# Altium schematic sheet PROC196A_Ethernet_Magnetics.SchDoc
size 431 x 279 mm; Date: Not shown in title block; ApprovedBy: Not shown in title block; CheckedBy: Not shown in title block; Author: Not shown in title block; CompanyName: Not shown in title block; Engineer: Not shown in title block; Organization: Not shown in title block; Address1: Not shown in title block; Address2: Not shown in title block; Address3: Not shown in title block; Address4: Not shown in title block; DocumentNumber: 13; Revision: Use project parameter SCH_Rev; SheetNumber: 13; SheetTotal: 25; PageSetup: Record=PageOptions¦CenterHorizontal=True¦CenterVertical=True¦PrintScale=1.00¦XCorrection=1.00¦YCorrection=1.00¦PrintKind=0¦BorderSize=5000000¦LeftOffset=0¦BottomOffset=0¦Orientation=2¦PaperLength=1000¦PaperWidth=1000¦Scale=100¦PaperSource=15¦PrintQuality=600¦MediaType=1¦DitherType=10¦PaperKind=Letter¦PrintScaleMode=1
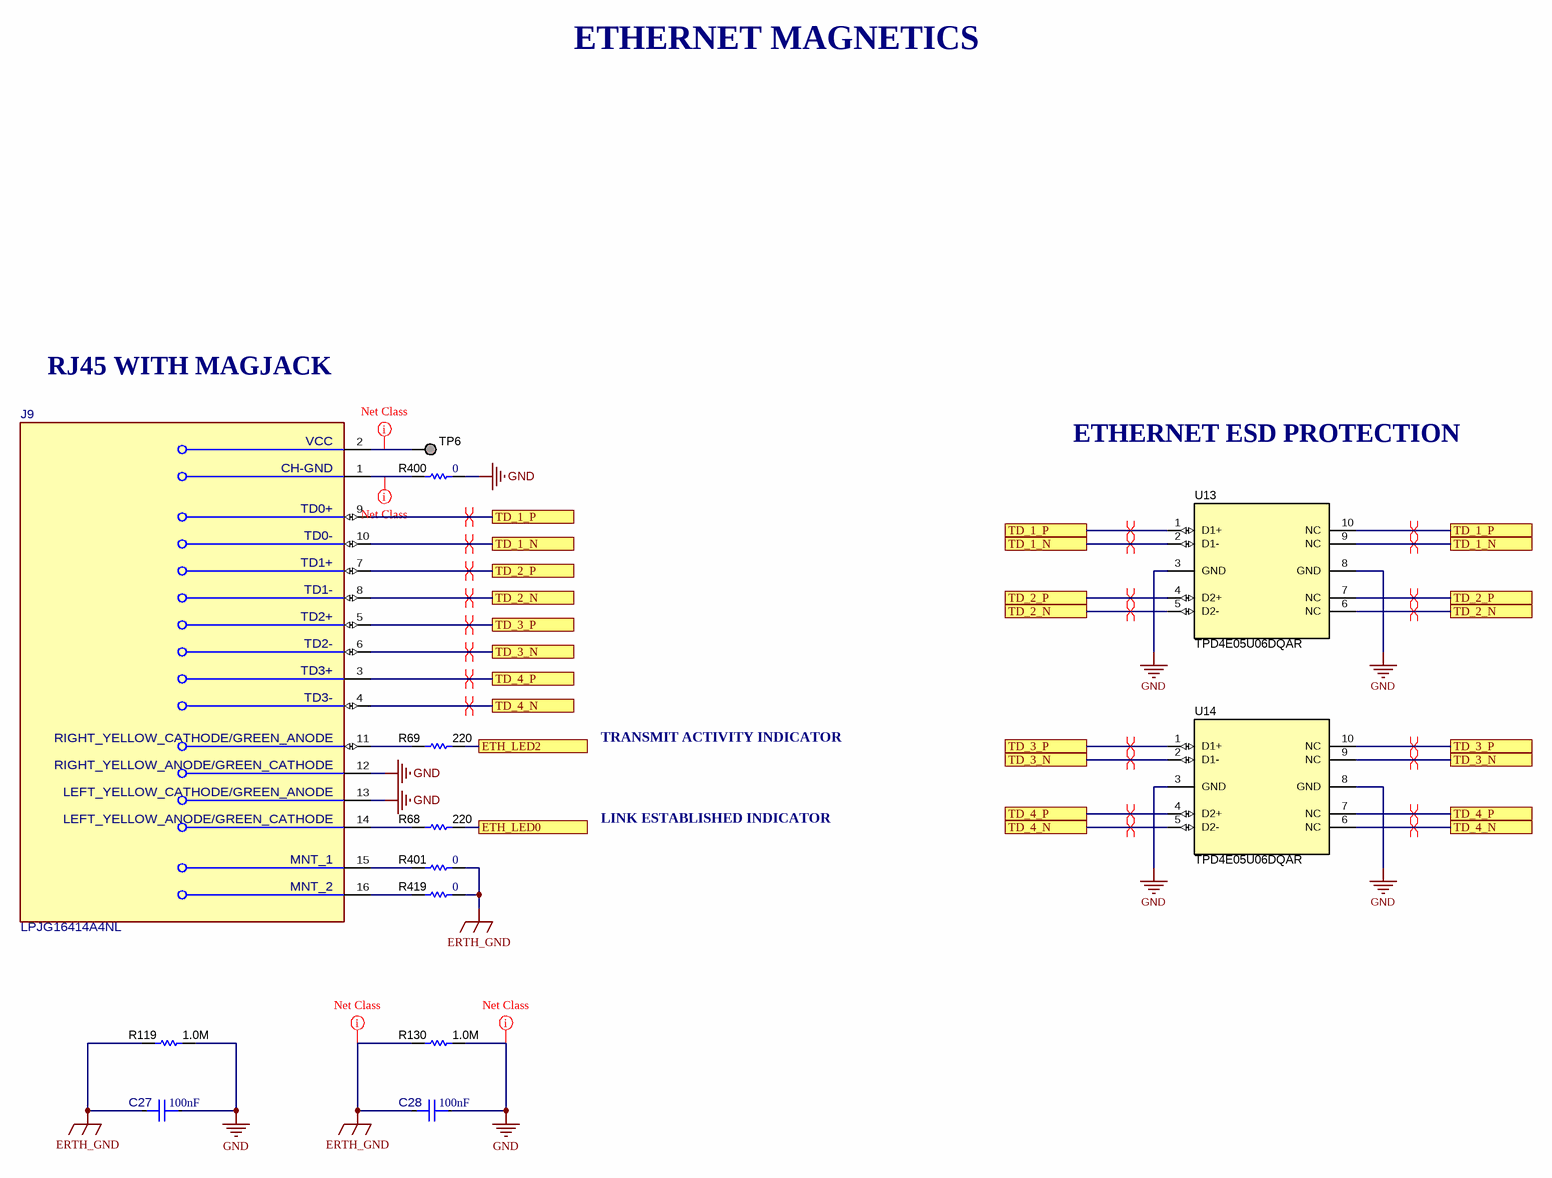
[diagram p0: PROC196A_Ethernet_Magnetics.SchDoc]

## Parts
C27  Cap_F: 100nF  [FP-C0603C104K4RACAUTO_0603-MFG]  (hidden comment: C0603C104K4RACAUTO)
C28  Cap_F: 100nF  [FP-C0603C104K4RACAUTO_0603-MFG]  (hidden comment: C0603C104K4RACAUTO)
J9  LPJG16414A4NL  [FP-LPJG16414A4NL_CONN_RJ45-MFG]
R68  ValueDisplayed: 220  [0402L]  (hidden comment: CRCW0402220RJNED)
R69  ValueDisplayed: 220  [0402L]  (hidden comment: CRCW0402220RJNED)
R119  ValueDisplayed: 1.0M  [1206L]  (hidden comment: CRCW12061M00JNEA)
R130  ValueDisplayed: 1.0M  [1206L]  (hidden comment: CRCW12061M00JNEA)
R400  ValueDisplayed: 0  [0402L]  (hidden comment: ERJ-2GE0R00X)
R401  ValueDisplayed: 0  [0402L]  (hidden comment: ERJ-2GE0R00X)
R419  ValueDisplayed: 0  [0402L]  (hidden comment: ERJ-2GE0R00X)
TP6  TESTPOINT  [TP_25MIL-SMT]  (value not drawn)  (no BOM)
U13  TPD4E05U06DQAR  [DQA0010A]
U14  TPD4E05U06DQAR  [DQA0010A]

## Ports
ETH_LED0, ETH_LED2, TD_1_N, TD_1_P, TD_2_N, TD_2_P, TD_3_N, TD_3_P, TD_4_N, TD_4_P

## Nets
ERTH_GND: C27.2 C28.2 R119.1 R130.1 R401.2 R419.2
GND: C27.1 C28.1 J9.12(RIGHT_YELLOW_ANODE/GREEN_CATHODE) J9.13(LEFT_YELLOW_CATHODE/GREEN_ANODE) R119.2 R130.2 R400.2 U13.3(GND) U13.8(GND) U14.3(GND) U14.8(GND)
ETH_LED0: R68.1 ; port ETH_LED0
ETH_LED2: R69.2 ; port ETH_LED2
TD_1_N: J9.10(TD0-) U13.2(D1-) U13.9(NC) ; port TD_1_N
TD_1_P: J9.9(TD0+) U13.1(D1+) U13.10(NC) ; port TD_1_P
TD_2_N: J9.8(TD1-) U13.5(D2-) U13.6(NC) ; port TD_2_N
TD_2_P: J9.7(TD1+) U13.4(D2+) U13.7(NC) ; port TD_2_P
TD_3_N: J9.6(TD2-) U14.2(D1-) U14.9(NC) ; port TD_3_N
TD_3_P: J9.5(TD2+) U14.1(D1+) U14.10(NC) ; port TD_3_P
TD_4_N: J9.4(TD3-) U14.5(D2-) U14.6(NC) ; port TD_4_N
TD_4_P: J9.3(TD3+) U14.4(D2+) U14.7(NC) ; port TD_4_P
NetJ9_1: J9.1(CH-GND) R400.1
NetJ9_2: J9.2(VCC) TP6.1
NetJ9_11: J9.11(RIGHT_YELLOW_CATHODE/GREEN_ANODE) R69.1
NetJ9_14: J9.14(LEFT_YELLOW_ANODE/GREEN_CATHODE) R68.2
NetJ9_15: J9.15(MNT_1) R401.1
NetJ9_16: J9.16(MNT_2) R419.1

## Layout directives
differential pair: TD_1_N, TD_1_P, TD_2_N, TD_2_P, TD_3_N, TD_3_P, TD_4_N, TD_4_P
net class PWR: ERTH_GND, GND, NetJ9_1, NetJ9_2

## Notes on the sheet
- ETHERNET MAGNETICS
- RJ45 WITH MAGJACK
- ETHERNET ESD PROTECTION
- TRANSMIT ACTIVITY INDICATOR
- LINK ESTABLISHED INDICATOR

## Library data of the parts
C27 C28 = CMP-0089508-1: C0603 0.10 μF X7R 30ppm/°C 10.00% 16 V; Manufacturer: KEMET; AEC Qualified: Yes; Tolerance_%: 0.1%; VDC_V: 16V; ValueDisplayed: 0.10 μF; AEC Grade: Grade 1; SizeZ_mm: 0.87mm
J9 = CMP-0088394-1: RJ45 Connector with 1000 Base-TX Inetgrated Magnetic; Manufacturer: LINK-PP; DUT-Pitch_mm: 1.27mm; Conn Orientation: Horizontal; ContactFinish: Gold; Conn Gender: Female; Is Female: yes; AEC Qualified: No; Shrouded: true
R68 R69 = CMP-0026878-3: RES, 220, 5%, 0.063 W, AEC-Q200 Grade 0, 0402; Manufacturer: Vishay-Dale; Power_W: 63mW; TempCo: 200 ppm/C; Value_Code: 220R; Value: 220; EIA_Code: E24; SizeX_mm: 1; SizeY_mm: 0.5; SizeZ_mm: 0.6; Value2: 0.063W; AEC Qualified: Y; VDC_V: 50V; AEC Category: Q200; AEC Grade: 0
R119 R130 = CMP-0018610-3: RES, 1.0 M, 5%, 0.25 W, AEC-Q200 Grade 0, 1206; Manufacturer: Vishay-Dale; Power_W: 250mW; TempCo: 200 ppm/C; Value_Code: 1M00; Value: 1.0Meg; EIA_Code: E24; Res_ohm: 1M; SizeX_mm: 3.2; SizeY_mm: 1.6; SizeZ_mm: 1.35; Value2: 0.25W; SizeArea_mm2: 5.12; AEC Qualified: Y; VDC_V: 200V; AEC Category: Q200; AEC Grade: 0
R400 R401 R419 = CMP-0026992-3: RES, 0, 5%, 0.1 W, AEC-Q200 Grade 0, 0402; Manufacturer: Panasonic; Power_W: 100mW; TempCo: 600 ppm/C; Value_Code: 0000; Value: 0; EIA_Code: E24; SizeX_mm: 1; SizeY_mm: 0.5; SizeZ_mm: 0.6; Value2: 0.1W; CompType: Resistor; AEC Qualified: Y; VDC_V: 50V; AEC Category: Q200; SizeAreaWB_mm2: 3; INSTALLATION: DNP
TP6 = CMP-0078143-3: TEST POINT.  No entry in BOM.
U13 U14 = CMP-0073613-3: 4-Channel Ultra-Low-Capacitance IEC ESD Protection Diode, DQA0010A (USON-10); Alternate Manufacturer: Texas Instruments; Green_Lifecycle: Active; SizeAreaWB_mm2: 7.0; Green_REACh: Passed; SizeZ_mm: 0.55; SizeX_mm: 1.0; SizeY_mm: 2.5; CompType: IC; AEC Category: Q200; AEC Qualified: N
